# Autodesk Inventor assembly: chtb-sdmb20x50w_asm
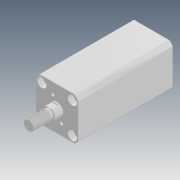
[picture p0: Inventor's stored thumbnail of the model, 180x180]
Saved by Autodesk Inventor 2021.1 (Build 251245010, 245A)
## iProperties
Company: Microsoft
Created: 2018-05
Part Number: chtb-sdmb20x50w_asm
Description: STEP AP214
Document SubType Name: Assembly
Designer: user
Title: chtb-sdmb20x50w_asm.STEP
Author: Windows
Revision Number: ÈÎºÎ
Sending System: SolidWorks 2015
Preprocessor: SwSTEP 2.0
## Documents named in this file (4)
- D:\Vault_2016\Projekty\Clamptek\Hydraulic\CHTB\CHTB-20\Inventor\CHTB-SDMB20x50W\chtb-sdmb20x50w_asm.iam
- D:\Vault_2016\Projekty\Clamptek\Hydraulic\CHTB\CHTB-20\Inventor\CHTB-SDMB20x50W\CHTB-SDMB20X50NBT.ipt
- D:\Vault_2016\Projekty\Clamptek\Hydraulic\CHTB\CHTB-20\Inventor\CHTB-SDMB20x50W\CHTB-SDMB20X50WHSG.ipt
- D:\Vault_2016\Projekty\Clamptek\Hydraulic\CHTB\CHTB-20\Inventor\CHTB-SDMB20x50W\QG_3.ipt
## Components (3 placed, 3 different names)
1. CHTB-SDMB20X50NBT_1
2. CHTB-SDMB20X50WHSG_2
3. QG_3_3
